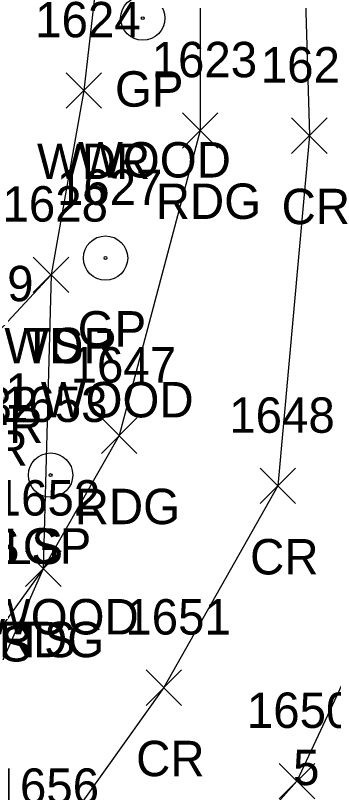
# Model space of a CAD drawing. Extents: x 1512665 to 1513714, y 110636 to 112816.
# Drawn here: x 1513104.16 to 1513122.08, y 110807.73 to 110851.61 of the extents above; entities that cross this region are included whole.
import ezdxf

# ---------------------------------------------------------------- set-up
doc = ezdxf.new("R2010")
doc.units = 0
for name, color, linetype in [('C_I', 7, 'Continuous'), ('L_A', 7, 'Continuous'), ('L_I', 7, 'Continuous'), ('L_TIC', 7, 'Continuous'), ('LAWA', 7, 'Continuous'), ('LELB', 7, 'Continuous'), ('P_A', 7, 'Continuous'), ('P_I', 7, 'Continuous'), ('P_TIC', 7, 'Continuous'), ('PEU', 7, 'Continuous'), ('PRC', 7, 'Continuous'), ('R_A', 7, 'Continuous'), ('R_C', 7, 'Continuous'), ('R_I', 7, 'Continuous'), ('RGP', 7, 'Continuous')]:
    doc.layers.add(name, color=color, linetype=linetype)

msp = doc.modelspace()

# ---------------------------------------------------------------- linework, layer by layer
at = {"layer": 'L_TIC'}
for points in [[(1513107.004, 110846.38), (1513109.004, 110848.38)], [(1513109.004, 110846.38), (1513107.004, 110848.38)], [(1513105.159, 110835.973), (1513107.159, 110837.973)], [(1513107.159, 110835.973), (1513105.159, 110837.973)], [(1513105.159, 110835.973), (1513107.159, 110837.973)], [(1513107.159, 110835.973), (1513105.159, 110837.973)], [(1513104.721, 110819.37), (1513106.721, 110821.37)], [(1513106.721, 110819.37), (1513104.721, 110821.37)]]:
    msp.add_lwpolyline(points, dxfattribs=at)
at = {"layer": 'LAWA'}
msp.add_lwpolyline([(1513113.578, 110922.99), (1513110.982, 110898.719), (1513111.08, 110874.171), (1513108.004, 110847.38), (1513106.159, 110836.973), (1513101.969, 110832.474), (1513101.106, 110831.183), (1513095.313, 110829.256)], dxfattribs=at)
at = {"layer": 'LELB'}
msp.add_lwpolyline([(1513106.159, 110836.973), (1513105.721, 110820.37), (1513099.343, 110811.519), (1513086.517, 110797.2)], dxfattribs=at)
at = {"layer": 'P_TIC'}
for points in [[(1513113.571, 110844.124), (1513115.571, 110846.124)], [(1513115.571, 110844.124), (1513113.571, 110846.124)], [(1513119.726, 110843.828), (1513121.726, 110845.828)], [(1513121.726, 110843.828), (1513119.726, 110845.828)], [(1513109.002, 110826.884), (1513111.002, 110828.884)], [(1513111.002, 110826.884), (1513109.002, 110828.884)], [(1513117.948, 110824.045), (1513119.948, 110826.045)], [(1513119.948, 110824.045), (1513117.948, 110826.045)], [(1513104.721, 110819.37), (1513106.721, 110821.37)], [(1513106.721, 110819.37), (1513104.721, 110821.37)], [(1513111.521, 110812.651), (1513113.521, 110814.651)], [(1513113.521, 110812.651), (1513111.521, 110814.651)], [(1513119.028, 110807.377), (1513121.028, 110809.377)], [(1513121.028, 110807.377), (1513119.028, 110809.377)]]:
    msp.add_lwpolyline(points, dxfattribs=at)
at = {"layer": 'PEU'}
for points in [[(1513166.519, 110981.347), (1513152.909, 110972.975), (1513141.651, 110962.521), (1513132.856, 110956.743), (1513121.044, 110940.287), (1513117.581, 110922.155), (1513113.236, 110898.634), (1513114.597, 110873.193), (1513114.571, 110845.124), (1513110.002, 110827.884), (1513105.721, 110820.37), (1513100.887, 110809.465), (1513086.517, 110797.2)], [(1513170.256, 110966.545), (1513161.211, 110960.303), (1513151.369, 110951.546), (1513143.018, 110943.811), (1513133.251, 110931.043), (1513127.426, 110919.762), (1513124.626, 110897.943), (1513124.876, 110872.667), (1513125.902, 110844.176), (1513126.27, 110821.797), (1513120.028, 110808.377), (1513110.828, 110798.027), (1513092.487, 110788.311), (1513089.551, 110792.994), (1513086.517, 110797.2)]]:
    msp.add_lwpolyline(points, dxfattribs=at)
at = {"layer": 'PRC'}
msp.add_lwpolyline([(1513199.52, 110982.675), (1513185.86, 110980.154), (1513168.393, 110974.825), (1513156.296, 110966.817), (1513145.568, 110957.841), (1513135.79, 110952.04), (1513127.966, 110935.792), (1513122.325, 110921.104), (1513118.394, 110897.939), (1513119.913, 110872.756), (1513120.726, 110844.828), (1513118.948, 110825.045), (1513112.521, 110813.651), (1513105.713, 110804.091), (1513089.551, 110792.994)], dxfattribs=at)
at = {"layer": 'RGP'}
for p, q in [((1513111.331, 110851.463), (1513111.331, 110851.463)), ((1513109.229, 110837.915), (1513109.229, 110837.915)), ((1513106.133, 110825.657), (1513106.133, 110825.657))]:
    msp.add_line(p, q, dxfattribs=at)
for centre, radius in [((1513111.331, 110851.463), 1.25), ((1513111.331, 110851.463), 0.0833), ((1513109.229, 110837.915), 1.25), ((1513109.229, 110837.915), 0.0833), ((1513106.133, 110825.657), 1.25), ((1513106.133, 110825.657), 0.0833)]:
    msp.add_circle(centre, radius, dxfattribs=at)

# ---------------------------------------------------------------- texts
at = {"layer": 'C_I'}
msp.add_text('5', height=2, dxfattribs=at).set_placement((1513119.807, 110808.146))
msp.add_text('5', height=2, dxfattribs=at).set_placement((1513119.807, 110808.146))
msp.add_text('5', height=2, dxfattribs=at).set_placement((1513119.807, 110808.146))
msp.add_text('5', height=2, dxfattribs=at).set_placement((1513119.807, 110808.146))
at = {"layer": 'L_A'}
for s, p in [('WDR', (1513105.366, 110842.38)), ('WDR', (1513103.521, 110831.973)), ('TS', (1513104.568, 110831.973)), ('WDR', (1513099.332, 110827.474)), ('WDR', (1513098.468, 110826.183)), ('WALLS', (1513097.768, 110820.629)), ('CS', (1513100.666, 110820.629)), ('WALLS', (1513096.018, 110815.13)), ('TS', (1513104.13, 110815.37))]:
    msp.add_text(s, height=2, dxfattribs=at).set_placement(p)
at = {"layer": 'L_I'}
for s, p in [('1624', (1513105.264, 110850.38)), ('1628', (1513103.419, 110839.973)), ('1628', (1513103.419, 110839.973)), ('1629', (1513099.221, 110835.474)), ('1629', (1513099.221, 110835.474)), ('1631', (1513099.127, 110829.402)), ('1632', (1513099.485, 110828.629)), ('1632', (1513099.485, 110828.629)), ('1652', (1513102.981, 110823.37))]:
    msp.add_text(s, height=2, dxfattribs=at).set_placement(p)
at = {"layer": 'P_A'}
for s, p in [('RDG', (1513112.059, 110840.124)), ('CR', (1513119.159, 110839.828)), ('RDG', (1513107.49, 110822.884)), ('CR', (1513117.381, 110820.045)), ('RDG', (1513103.209, 110815.37)), ('CR', (1513110.954, 110808.651))]:
    msp.add_text(s, height=2, dxfattribs=at).set_placement(p)
at = {"layer": 'P_I'}
for s, p in [('1623', (1513111.831, 110848.124)), ('1622', (1513117.986, 110847.828)), ('1647', (1513107.262, 110830.884)), ('1648', (1513116.208, 110828.045)), ('1652', (1513102.981, 110823.37)), ('1651', (1513110.347, 110816.651)), ('1650', (1513117.201, 110811.377)), ('1656', (1513102.917, 110807.091))]:
    msp.add_text(s, height=2, dxfattribs=at).set_placement(p)
at = {"layer": 'R_A'}
for p in [(1513109.764, 110846.463), (1513107.662, 110832.915), (1513104.566, 110820.657)]:
    msp.add_text('GP', height=2, dxfattribs=at).set_placement(p)
at = {"layer": 'R_C'}
for p in [(1513107.685, 110842.463), (1513105.583, 110828.915), (1513102.488, 110816.657)]:
    msp.add_text('WOOD', height=2, dxfattribs=at).set_placement(p)
at = {"layer": 'R_I'}
for s, p in [('1627', (1513106.489, 110840.915)), ('1653', (1513103.393, 110828.657))]:
    msp.add_text(s, height=2, dxfattribs=at).set_placement(p)

doc.saveas('drawing.dxf')
